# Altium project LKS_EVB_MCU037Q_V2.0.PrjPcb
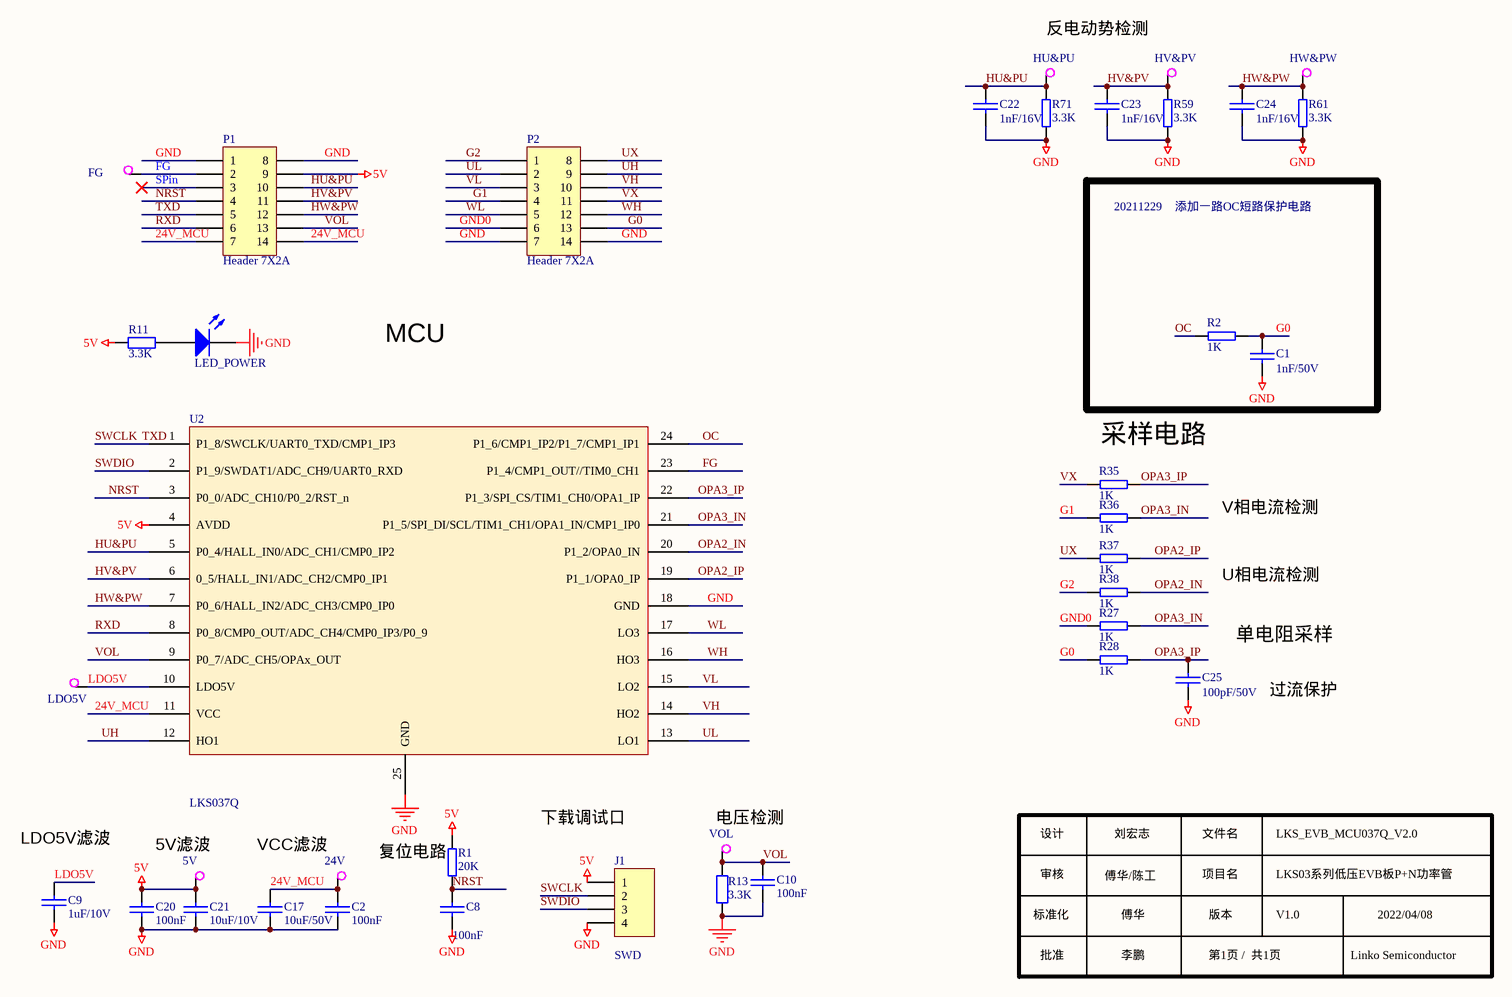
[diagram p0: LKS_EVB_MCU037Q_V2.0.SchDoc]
1 sheet, 38 parts. Net scope: global (net labels, ports and power ports of the same name join across sheets).
Board file: LKS_EVB_MCU037Q_V2.0.PcbDoc

## Sheet LKS_EVB_MCU037Q_V2.0.SchDoc: LKS087_DEMO_V2.0_200109
size A3; Revision: V1.0; SheetNumber: 1; SheetTotal: 1

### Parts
5V  TestP  [TP-40]  (value not drawn)
24V  TestP  [TP-40]  (value not drawn)
C1  1nF/50V  [0805C]
C2  100nF  [0805C]
C8  100nF  [0805C]
C9  1uF/10V  [0805C]
C10  100nF  [0805C]
C17  10uF/50V  [1206]
C20  100nF  [0805C]
C21  10uF/10V  [0805C]
C22  1nF/16V  [0805C]
C23  1nF/16V  [0805C]
C24  1nF/16V  [0805C]
C25  100pF/50V  [0805C]
FG  TestP  [TP-40]  (value not drawn)
HU&PU  TestP  [TP-40]  (value not drawn)
HV&PV  TestP  [TP-40]  (value not drawn)
HW&PW  TestP  [TP-40]  (value not drawn)
J1  SWD  [SIP4-2.5]
LDO5V  TestP  [TP-40]  (value not drawn)
LED_POWER  (no value)  [0805D]
P1  Header 7X2A  [HDR2X7_CEN]
P2  Header 7X2A  [HDR2X7_CEN]
R1  20K  [0805R]
R2  1K  [0805R]
R11  3.3K  [0603R]
R13  3.3K  [0805R]
R27  1K  [0805R]
R28  1K  [0805R]
R35  1K  [0805R]
R36  1K  [0805R]
R37  1K  [0805R]
R38  1K  [0805R]
R59  3.3K  [0805R]
R61  3.3K  [0805R]
R71  3.3K  [0805R]
U2  LKS037Q  [QFN24]
VOL  TestP  [TP-40]  (value not drawn)

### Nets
5V: 5V.1 C20.1 C21.1 J1.1 P1.9 R1.1 R11.2 U2.4(AVDD)
GND: C1.1 C2.2 C8.2 C9.2 C10.2 C17.1 C20.2 C21.2 C22.1 C23.1 C24.1 C25.1 J1.4 LED_POWER.2(K) P1.1 P1.8 P2.7 P2.14 R13.2 R59.1 R61.1 R71.1 U2.18(GND) U2.25(GND)
24V_MCU: 24V.1 C2.1 C17.2 P1.7 P1.14 U2.11(VCC)
FG: FG.1 P1.2 U2.23(P1_4/CMP1_OUT//TIM0_CH1)
G0: C1.2 P2.13 R2.1 R28.2
G1: P2.4 R36.1
G2: P2.1 R38.1
GND0: P2.6 R27.2
HU&PU: C22.2 HU&PU.1 P1.10 R71.2 U2.5(P0_4/HALL_IN0/ADC_CH1/CMP0_IP2)
HV&PV: C23.2 HV&PV.1 P1.11 R59.2 U2.6(0_5/HALL_IN1/ADC_CH2/CMP0_IP1)
HW&PW: C24.2 HW&PW.1 P1.12 R61.2 U2.7(P0_6/HALL_IN2/ADC_CH3/CMP0_IP0)
LDO5V: C9.1 LDO5V.1 U2.10(LDO5V)
NRST: C8.1 P1.4 R1.2 U2.3(P0_0/ADC_CH10/P0_2/RST_n)
OC: R2.2 U2.24(P1_6/CMP1_IP2/P1_7/CMP1_IP1)
OPA2_IN: R38.2 U2.20(P1_2/OPA0_IN)
OPA2_IP: R37.2 U2.19(P1_1/OPA0_IP)
OPA3_IN: R27.1 R36.2 U2.21(P1_5/SPI_DI/SCL/TIM1_CH1/OPA1_IN/CMP1_IP0)
OPA3_IP: C25.2 R28.1 R35.2 U2.22(P1_3/SPI_CS/TIM1_CH0/OPA1_IP)
RXD: P1.6 U2.8(P0_8/CMP0_OUT/ADC_CH4/CMP0_IP3/P0_9)
SPin: P1.3
SWCLK: J1.2 P1.5 U2.1(P1_8/SWCLK/UART0_TXD/CMP1_IP3)  [also labelled TXD]
SWDIO: J1.3 U2.2(P1_9/SWDAT1/ADC_CH9/UART0_RXD)
UH: P2.9 U2.12(HO1)
UL: P2.2 U2.13(LO1)
UX: P2.8 R37.1
VH: P2.10 U2.14(HO2)
VL: P2.3 U2.15(LO2)
VOL: C10.1 P1.13 R13.1 U2.9(P0_7/ADC_CH5/OPAx_OUT) VOL.1
VX: P2.11 R35.1
WH: P2.12 U2.16(HO3)
WL: P2.5 U2.17(LO3)
NetLED_POWER_1: LED_POWER.1(A) R11.1

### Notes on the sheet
- 20211229
- 添加一路OC短路保护电路
- MCU
- (near R35) 采样电路
- V相电流检测
- U相电流检测
- 过流保护
- (near C9) LDO5V滤波
- (near 5V) 5V滤波
- VCC滤波
- 复位电路
- 设计
- 审核
- 傅华/陈工
- 刘宏志
- 文件名
- 项目名
- LKS_EVB_MCU037Q_V2.0
- LKS03系列低压EVB板P+N功率管
- 标准化
- 批准
- 傅华
- 李鹏
- 版本
- 第1页 /  共1页
- V1.0
- Linko Semiconductor
- 2022/04/08
- Labels drawn without touching a wire or pin: 下载调试口, 单电阻采样, 反电动势检测, 电压检测

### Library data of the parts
C1 C8 C9 C20-C25 = C: Capacitor
C2 C10 C17 = CAP: Capacitor
J1 = Header 4: Header, 4-Pin
LED_POWER = LED2: Typical RED, GREEN, YELLOW, AMBER GaAs LED
P1 P2 = Header 7X2A: Header, 7-Pin, Dual row
R1 R2 R27 R28 R35-R38 = RES2-1
R11 R13 = Res2: Resistor
R59 R61 R71 = RES/1
U2 = LKS32MC037QM6Q8: CHIP--ldo-QFN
